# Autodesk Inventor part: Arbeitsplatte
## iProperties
Shininess: 64.0
Length Units: 11269
Angle Units: 11279
Time Units: 11290
Mass Units: 11283
Length Display Precision: 3
Angle Display Precision: 2
Compacted: True
Part Number: Arbeitsplatte
Document SubType Name: Modeling
Created: 2003-05
Material: Standard
Designer: chefe
Density: 0.0
Volumn: 0.0
Area: 0.0
PropertySet Name: Model Information
Control State: 0
Master: False
Checked Out: False
Author: chefe
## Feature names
1. Extrusion1
2. Extrusion2
